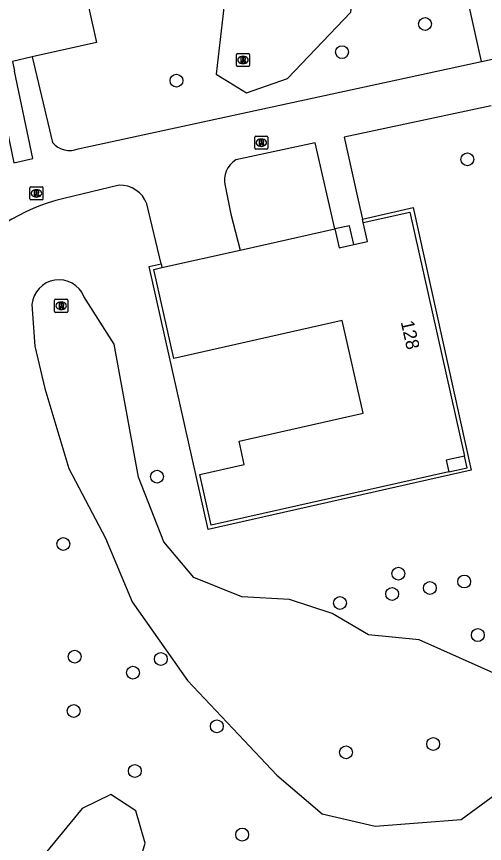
# Model space of a CAD drawing. Extents: x 156664 to 157568, y 383571 to 384421.
# Drawn here: x 156758.2 to 156793.8, y 383881.2 to 383944.2 of the extents above; entities that cross this region are included whole.
import ezdxf

# ---------------------------------------------------------------- set-up
doc = ezdxf.new("R2010")
doc.units = 0
for name, color, linetype in [('IMGEO_Boom', 7, 'Continuous'), ('IMGEO_Groenvoorziening', 7, 'Continuous'), ('IMGEO_Meer_plas_ven_vijver', 7, 'Continuous'), ('IMGEO_Pand', 7, 'Continuous'), ('IMGEO_Pand_nummerreeks', 7, 'Continuous'), ('IMGEO_Pand_overbouw', 7, 'Continuous'), ('IMGEO_Rijbaan_lokaal_gesloten', 7, 'Continuous'), ('IMGEO_Rioolput', 7, 'Continuous'), ('IMGEO_Voetpad_open', 7, 'Continuous')]:
    doc.layers.add(name, color=color, linetype=linetype)

msp = doc.modelspace()

# ---------------------------------------------------------------- linework, layer by layer
at = {"layer": 'IMGEO_Boom'}
for centre in [(156789.312, 383943.613), (156782.999, 383941.466), (156770.4, 383939.3), (156792.529, 383933.304), (156768.925, 383909.156), (156761.792, 383904.036), (156787.283, 383901.774), (156792.293, 383901.175), (156786.807, 383900.229), (156789.68, 383900.681), (156782.842, 383899.539), (156793.327, 383897.097), (156762.662, 383895.46), (156769.21, 383895.271), (156767.091, 383894.232), (156762.584, 383891.322), (156773.472, 383890.158), (156789.932, 383888.802), (156783.301, 383888.177), (156767.234, 383886.756), (156775.401, 383881.913)]:
    msp.add_circle(centre, 0.489, dxfattribs=at)
at = {"layer": 'IMGEO_Groenvoorziening'}
for points in [[(156784.555, 383928.753), (156788.41, 383929.644), (156792.818, 383909.646), (156772.807, 383905.13), (156768.321, 383925.155), (156769.229, 383925.367)], [(156767.313, 383878.874), (156768.021, 383881.267), (156767.299, 383883.721), (156765.415, 383884.973), (156763.24, 383883.907), (156760.194, 383880.185), (156759.562, 383879.076), (156758.573, 383877.099), (156759.648, 383875.982), (156760.744, 383872.951), (156764.354, 383873.446), (156767.313, 383878.874)]]:
    msp.add_lwpolyline(points, dxfattribs=at)
at = {"layer": 'IMGEO_Meer_plas_ven_vijver'}
for points in [[(156779.327, 383973.994), (156777.149, 383975.302), (156776.217, 383977.176), (156774.697, 383978.591), (156770.374, 383978.421), (156769.264, 383975.956), (156770.584, 383973.827), (156772.059, 383971.514), (156773.11, 383969.336), (156773.363, 383966.149), (156772.286, 383960.331), (156772.527, 383958.648), (156773.33, 383956.082), (156775.033, 383949.232), (156774.037, 383945.068), (156773.42, 383939.788), (156775.723, 383938.382), (156778.843, 383939.451), (156783.667, 383944.503), (156783.962, 383947.12)], [(156782.244, 383898.751), (156779.003, 383899.812), (156775.366, 383900.016), (156771.726, 383901.474), (156769.434, 383904.195), (156767.525, 383909.129), (156765.651, 383919.251), (156763.361, 383922.88)], [(156759.409, 383922.264), (156759.636, 383919.089), (156760.391, 383915.857), (156762.212, 383909.779), (156764.997, 383904.478), (156767.023, 383899.625), (156771.252, 383893.646), (156775.121, 383889.52), (156778.043, 383886.426), (156781.482, 383883.503), (156785.522, 383882.557), (156792.055, 383883.073), (156795.493, 383885.566), (156797.298, 383887.371), (156797.126, 383892.013), (156795.235, 383893.904), (156788.874, 383896.741), (156785.006, 383897.128), (156782.244, 383898.751)]]:
    msp.add_lwpolyline(points, dxfattribs=at)
msp.add_arc((156761.462, 383922.078), 2.061, 22.89543, 174.82343, dxfattribs=at)
at = {"layer": 'IMGEO_Pand'}
for points in [[(156761.956, 383955.261), (156762.554, 383952.572), (156762.026, 383952.455), (156764.312, 383942.195), (156759.416, 383941.099)], [(156759.416, 383941.099), (156757.925, 383940.765), (156758.081, 383940.019)], [(156784.613, 383928.493), (156788.143, 383929.281), (156792.312, 383910.722), (156790.931, 383910.412), (156791.131, 383909.52), (156773.05, 383905.464), (156772.187, 383909.327), (156775.564, 383910.081), (156775.168, 383911.852), (156784.613, 383913.976), (156783.017, 383921.041), (156770.213, 383918.148), (156768.69, 383924.935), (156769.3, 383925.071)], [(156782.461, 383928.012), (156782.78, 383926.578), (156783.882, 383926.824), (156784.932, 383927.058), (156784.613, 383928.493)], [(156775.245, 383926.4), (156782.461, 383928.012)], [(156769.3, 383925.071), (156775.245, 383926.4)]]:
    msp.add_lwpolyline(points, dxfattribs=at)
at = {"layer": 'IMGEO_Pand_overbouw'}
for points in [[(156783.563, 383928.258), (156782.461, 383928.012), (156782.78, 383926.578), (156783.882, 383926.824)], [(156792.312, 383910.722), (156790.931, 383910.412), (156791.131, 383909.52), (156792.512, 383909.829)]]:
    msp.add_lwpolyline(points, close=True, dxfattribs=at)
at = {"layer": 'IMGEO_Rijbaan_lokaal_gesloten'}
for points in [[(156759.416, 383941.099), (156760.97, 383934.592)], [(156793.6, 383940.758), (156795.59, 383941.189)], [(156762.934, 383934.118), (156793.6, 383940.758)], [(156756.644, 383939.698), (156758.042, 383933.044), (156759.476, 383933.381), (156758.081, 383940.019)], [(156794.353, 383937.37), (156783.169, 383934.99), (156784.232, 383930.211), (156784.555, 383928.753)], [(156782.461, 383928.012), (156780.961, 383934.576), (156774.922, 383933.277)], [(156766.03, 383931.333), (156761.825, 383930.332)], [(156774.107, 383931.292), (156774.533, 383929.146), (156775.245, 383926.4)], [(156769.229, 383925.367), (156768.136, 383929.92)], [(156784.613, 383928.493), (156784.555, 383928.753)], [(156769.229, 383925.367), (156769.3, 383925.071)]]:
    msp.add_lwpolyline(points, dxfattribs=at)
for centre, radius, start, end in [((156762.262, 383935.638), 1.662, 219.00126, 293.86167), ((156775.898, 383931.716), 1.841, 122.03016, 193.32576), ((156766.126, 383929.2), 2.135, 19.70299, 92.57851), ((156765.181, 383916.263), 14.464, 103.41782, 179.48447)]:
    msp.add_arc(centre, radius, start, end, dxfattribs=at)
at = {"layer": 'IMGEO_Rioolput'}
for p, q in [((156774.963, 383940.447), (156774.963, 383941.299)), ((156775.038, 383941.373), (156775.89, 383941.373)), ((156775.451, 383941.153), (156775.476, 383941.153)), ((156775.964, 383941.299), (156775.964, 383940.447)), ((156775.89, 383940.373), (156775.038, 383940.373)), ((156775.474, 383940.593), (156775.449, 383940.593)), ((156776.354, 383934.15), (156776.354, 383935.002)), ((156776.429, 383935.076), (156777.281, 383935.076)), ((156776.842, 383934.856), (156776.867, 383934.856)), ((156777.355, 383935.002), (156777.355, 383934.15)), ((156777.281, 383934.076), (156776.429, 383934.076)), ((156776.865, 383934.296), (156776.84, 383934.296)), ((156759.247, 383930.291), (156759.247, 383931.143)), ((156759.322, 383931.217), (156760.174, 383931.217)), ((156759.735, 383930.997), (156759.76, 383930.997)), ((156760.248, 383931.143), (156760.248, 383930.291)), ((156759.758, 383930.437), (156759.733, 383930.437)), ((156760.174, 383930.217), (156759.322, 383930.217)), ((156761.132, 383921.734), (156761.132, 383922.586)), ((156761.207, 383922.66), (156762.059, 383922.66)), ((156761.62, 383922.44), (156761.645, 383922.44)), ((156762.133, 383922.586), (156762.133, 383921.734)), ((156762.059, 383921.66), (156761.207, 383921.66)), ((156761.643, 383921.88), (156761.618, 383921.88))]:
    msp.add_line(p, q, dxfattribs=at)
for points in [[(156774.963, 383940.447), (156774.963, 383941.299)], [(156775.038, 383941.373), (156775.89, 383941.373)], [(156775.552, 383941.071), (156775.3, 383941.073), (156775.3, 383940.673)], [(156775.478, 383940.992), (156775.424, 383940.992), (156775.424, 383940.911)], [(156775.964, 383941.299), (156775.964, 383940.447)], [(156775.89, 383940.373), (156775.038, 383940.373)], [(156775.3, 383940.673), (156775.424, 383940.673), (156775.424, 383940.835), (156775.435, 383940.835)], [(156775.424, 383940.911), (156775.476, 383940.911)], [(156775.482, 383940.806), (156775.553, 383940.673), (156775.693, 383940.673), (156775.628, 383940.799)], [(156776.354, 383934.15), (156776.354, 383935.002)], [(156776.429, 383935.076), (156777.281, 383935.076)], [(156776.943, 383934.774), (156776.691, 383934.776), (156776.691, 383934.376)], [(156776.869, 383934.695), (156776.815, 383934.695), (156776.815, 383934.614)], [(156777.355, 383935.002), (156777.355, 383934.15)], [(156777.281, 383934.076), (156776.429, 383934.076)], [(156776.691, 383934.376), (156776.815, 383934.376), (156776.815, 383934.538), (156776.826, 383934.538)], [(156776.815, 383934.614), (156776.867, 383934.614)], [(156776.873, 383934.509), (156776.944, 383934.376), (156777.084, 383934.376), (156777.019, 383934.502)], [(156759.247, 383930.291), (156759.247, 383931.143)], [(156759.322, 383931.217), (156760.174, 383931.217)], [(156759.836, 383930.915), (156759.584, 383930.917), (156759.584, 383930.517)], [(156760.248, 383931.143), (156760.248, 383930.291)], [(156759.584, 383930.517), (156759.708, 383930.517), (156759.708, 383930.679), (156759.719, 383930.679)], [(156759.762, 383930.836), (156759.708, 383930.836), (156759.708, 383930.755)], [(156759.708, 383930.755), (156759.76, 383930.755)], [(156759.766, 383930.65), (156759.837, 383930.517), (156759.977, 383930.517), (156759.912, 383930.643)], [(156760.174, 383930.217), (156759.322, 383930.217)], [(156761.132, 383921.734), (156761.132, 383922.586)], [(156761.207, 383922.66), (156762.059, 383922.66)], [(156761.721, 383922.358), (156761.469, 383922.36), (156761.469, 383921.96)], [(156761.469, 383921.96), (156761.593, 383921.96), (156761.593, 383922.122), (156761.604, 383922.122)], [(156761.647, 383922.279), (156761.593, 383922.279), (156761.593, 383922.198)], [(156761.593, 383922.198), (156761.645, 383922.198)], [(156761.651, 383922.093), (156761.722, 383921.96), (156761.862, 383921.96), (156761.797, 383922.086)], [(156762.133, 383922.586), (156762.133, 383921.734)], [(156762.059, 383921.66), (156761.207, 383921.66)]]:
    msp.add_lwpolyline(points, dxfattribs=at)
for centre, radius, start, end in [((156775.04, 383941.297), 0.0765, 91.55205, 178.44795), ((156775.04, 383941.297), 0.0765, 91.55205, 178.44795), ((156775.484, 383940.896), 0.0964, 77.00612, 93.18647), ((156775.498, 383940.953), 0.0378, 276.66336, 79.67722), ((156775.551, 383940.961), 0.109, 350.36119, 89.41601), ((156775.549, 383940.961), 0.112, 277.58423, 350.98172), ((156775.888, 383941.297), 0.0765, 1.55205, 88.44795), ((156775.888, 383941.297), 0.0765, 1.55205, 88.44795), ((156775.04, 383940.449), 0.0765, 181.55205, 268.44795), ((156775.04, 383940.449), 0.0765, 181.55205, 268.44795), ((156775.434, 383940.782), 0.0533, 26.02933, 88.69889), ((156775.46, 383941.1), 0.19, 274.7715, 282.96867), ((156775.533, 383940.746), 0.108, 29.51342, 73.79051), ((156775.888, 383940.449), 0.0765, 271.55205, 358.44795), ((156775.888, 383940.449), 0.0765, 271.55205, 358.44795), ((156776.431, 383935), 0.0765, 91.55205, 178.44795), ((156776.431, 383935), 0.0765, 91.55205, 178.44795), ((156776.875, 383934.599), 0.0964, 77.00612, 93.18647), ((156776.889, 383934.656), 0.0378, 276.66336, 79.67722), ((156776.942, 383934.664), 0.109, 350.36119, 89.41601), ((156776.94, 383934.664), 0.112, 277.58423, 350.98172), ((156777.279, 383935), 0.0765, 1.55205, 88.44795), ((156777.279, 383935), 0.0765, 1.55205, 88.44795), ((156776.431, 383934.152), 0.0765, 181.55205, 268.44795), ((156776.431, 383934.152), 0.0765, 181.55205, 268.44795), ((156776.825, 383934.485), 0.0533, 26.02933, 88.69889), ((156776.851, 383934.803), 0.19, 274.7715, 282.96867), ((156776.924, 383934.449), 0.108, 29.51342, 73.79051), ((156777.279, 383934.152), 0.0765, 271.55205, 358.44795), ((156777.279, 383934.152), 0.0765, 271.55205, 358.44795), ((156759.324, 383931.141), 0.0765, 91.55205, 178.44795), ((156759.324, 383931.141), 0.0765, 91.55205, 178.44795), ((156759.835, 383930.805), 0.109, 350.36119, 89.41601), ((156760.172, 383931.141), 0.0765, 1.55205, 88.44795), ((156760.172, 383931.141), 0.0765, 1.55205, 88.44795), ((156759.324, 383930.293), 0.0765, 181.55205, 268.44795), ((156759.324, 383930.293), 0.0765, 181.55205, 268.44795), ((156759.718, 383930.626), 0.0533, 26.02933, 88.69889), ((156759.744, 383930.944), 0.19, 274.7715, 282.96867), ((156759.768, 383930.74), 0.0964, 77.00612, 93.18647), ((156759.782, 383930.797), 0.0378, 276.66336, 79.67722), ((156759.833, 383930.805), 0.112, 277.58423, 350.98172), ((156759.817, 383930.59), 0.108, 29.51342, 73.79051), ((156760.172, 383930.293), 0.0765, 271.55205, 358.44795), ((156760.172, 383930.293), 0.0765, 271.55205, 358.44795), ((156761.209, 383922.584), 0.0765, 91.55205, 178.44795), ((156761.209, 383922.584), 0.0765, 91.55205, 178.44795), ((156761.603, 383922.069), 0.0533, 26.02933, 88.69889), ((156761.629, 383922.387), 0.19, 274.7715, 282.96867), ((156761.653, 383922.183), 0.0964, 77.00612, 93.18647), ((156761.667, 383922.24), 0.0378, 276.66336, 79.67722), ((156761.72, 383922.248), 0.109, 350.36119, 89.41601), ((156761.718, 383922.248), 0.112, 277.58423, 350.98172), ((156761.702, 383922.033), 0.108, 29.51342, 73.79051), ((156762.057, 383922.584), 0.0765, 1.55205, 88.44795), ((156762.057, 383922.584), 0.0765, 1.55205, 88.44795), ((156761.209, 383921.736), 0.0765, 181.55205, 268.44795), ((156761.209, 383921.736), 0.0765, 181.55205, 268.44795), ((156762.057, 383921.736), 0.0765, 271.55205, 358.44795), ((156762.057, 383921.736), 0.0765, 271.55205, 358.44795)]:
    msp.add_arc(centre, radius, start, end, dxfattribs=at)
for centre, major_axis, ratio, start_param, end_param in [((156775.45, 383940.873), (-0.387, 0.002), 0.722429, 4.712389, 7.853982), ((156775.475, 383940.873), (-0.39, 0.002), 0.717154, 1.570796, 4.712389), ((156776.841, 383934.576), (-0.387, 0.002), 0.722429, 4.712389, 7.853982), ((156776.866, 383934.576), (-0.39, 0.002), 0.717154, 1.570796, 4.712389), ((156759.734, 383930.717), (-0.387, 0.002), 0.722429, 4.712389, 7.853982), ((156759.759, 383930.717), (-0.39, 0.002), 0.717154, 1.570796, 4.712389), ((156761.619, 383922.16), (-0.387, 0.002), 0.722429, 4.712389, 7.853982), ((156761.644, 383922.16), (-0.39, 0.002), 0.717154, 1.570796, 4.712389)]:
    msp.add_ellipse(centre, major_axis=major_axis, ratio=ratio, start_param=start_param, end_param=end_param, dxfattribs=at)
at = {"layer": 'IMGEO_Voetpad_open'}
msp.add_lwpolyline([(156793.6, 383940.758), (156778.599, 384008.292)], dxfattribs=at)

# ---------------------------------------------------------------- texts
at = {"layer": 'IMGEO_Pand_nummerreeks'}
msp.add_text('128', height=1, rotation=282.66216, dxfattribs=at).set_placement((156787.457, 383920.927))

doc.saveas('drawing.dxf')
